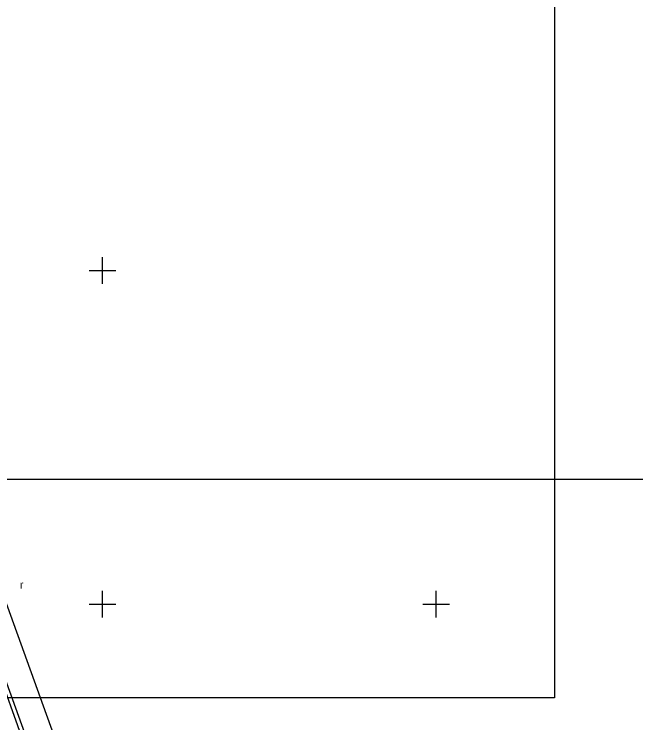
# Model space of a CAD drawing. Extents: x -612546 to -611926, y -1201932 to -1200444.
# Drawn here: x -612313.2 to -612220.1, y -1200867.8 to -1200761.6 of the extents above; entities that cross this region are included whole.
import ezdxf

# ---------------------------------------------------------------- set-up
doc = ezdxf.new("R2010")
doc.units = 0
for name, color, linetype in [('14 hrana pata svahu', 7, 'Continuous'), ('61 legenda křížky', 7, 'Continuous'), ('Hranice parcel', 7, 'Continuous'), ('Vrstva 36', 7, 'Continuous'), ('Vrstva 63', 7, 'Continuous')]:
    doc.layers.add(name, color=color, linetype=linetype)

msp = doc.modelspace()

# ---------------------------------------------------------------- linework, layer by layer
at = {"layer": '14 hrana pata svahu'}
msp.add_lwpolyline([(-612115.84, -1201111.42), (-612142.3, -1201080.92), (-612162.58, -1201054.92), (-612187.22, -1201025.94), (-612211.45, -1200996.73), (-612237.71, -1200968.13), (-612275.47, -1200925.26), (-612297.25, -1200898.18), (-612305.42, -1200888.34), (-612310.59, -1200874.11), (-612323.74, -1200837.38), (-612336.44, -1200801.43), (-612350.12, -1200764.09), (-612361.57, -1200731.35), (-612377.95, -1200692.77), (-612388.38, -1200663.69), (-612401.66, -1200625.89), (-612414.44, -1200590.59), (-612427.78, -1200553.92), (-612436.33, -1200532.1), (-612442.76, -1200519.02), (-612455.83, -1200502.43), (-612463.71, -1200487.36), (-612471.87, -1200478.15)], dxfattribs=at)
at = {"layer": '61 legenda křížky'}
for p, q in [((-612300, -1200802), (-612300, -1200798)), ((-612302, -1200800), (-612298, -1200800)), ((-612300, -1200852), (-612300, -1200848)), ((-612250, -1200852), (-612250, -1200848)), ((-612302, -1200850), (-612298, -1200850)), ((-612252, -1200850), (-612248, -1200850))]:
    msp.add_line(p, q, dxfattribs=at)
at = {"layer": 'Hranice parcel'}
for points in [[(-612424.14, -1200544.19), (-612385.56, -1200652.97), (-612376.97, -1200665.68), (-612365.31, -1200671.92), (-612359.59, -1200681.01), (-612363.6, -1200702.67), (-612362.5, -1200716.42), (-612304.9, -1200876.31), (-612299.88, -1200886.48), (-612289.63, -1200899.21), (-612225.19, -1200972.6)], [(-612367.63, -1200702.46), (-612366.44, -1200717.27), (-612308.59, -1200877.88), (-612303.27, -1200888.65), (-612292.69, -1200901.79), (-612203.37, -1201003.51), (-612163.72, -1201050.75), (-612139.89, -1201080.24), (-612084.23, -1201147.54), (-612068.31, -1201163.86)]]:
    msp.add_lwpolyline(points, dxfattribs=at)
at = {"layer": 'Vrstva 63'}
for p, q in [((-612232.3, -1200444.06), (-612232.3, -1200864.06)), ((-612359.93, -1200831.26), (-612062.93, -1200831.26)), ((-612232.3, -1200864.06), (-612529.3, -1200864.06))]:
    msp.add_line(p, q, dxfattribs=at)

# ---------------------------------------------------------------- texts
at = {"layer": 'Vrstva 36'}
msp.add_text('r', height=1.2, dxfattribs=at).set_placement((-612312.38, -1200847.69))

doc.saveas('drawing.dxf')
